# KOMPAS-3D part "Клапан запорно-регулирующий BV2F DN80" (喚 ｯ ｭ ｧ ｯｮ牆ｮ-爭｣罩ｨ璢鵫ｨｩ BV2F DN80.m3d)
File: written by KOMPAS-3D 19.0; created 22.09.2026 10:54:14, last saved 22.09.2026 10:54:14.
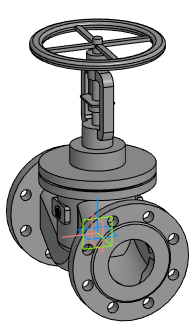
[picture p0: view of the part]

Document properties: Автор: Энергия; Полное имя файла: Z:\3.Личные\sachek\Dendor\_3D для проектировщиков\5.7 Клапан запорно-регулирующий BV2F\BV2F_STP\Клапан запорно-регулирующий BV2F DN80.m3d

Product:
- Part/product: Клапан запорно-регулирующий BV2F DN80

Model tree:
1. Операция без истории:1  (labels: Клапан запорно-регулирующий BV2F DN80)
